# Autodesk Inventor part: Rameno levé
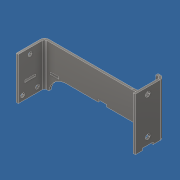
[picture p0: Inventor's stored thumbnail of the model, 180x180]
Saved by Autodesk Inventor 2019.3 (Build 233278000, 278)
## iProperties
Created: 2019-02
Part Number: Rameno levé
Material: Nerezová ocel, austenitická
Document SubType Name: Plech
Designer: B-hon
Density: 8 g/cm^3
Sheet Metal Rule: Výchozí_mm
Appearance: Pololeštěná
Author: B-hon
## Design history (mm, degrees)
node "Plocha3"
  sketch "Náčrt4"
    geometry: L1 (0, 0)-(169, 0); L2 (169, 0)-(169, 95); L3 (169, 95)-(0, 95); L4 (0, 95)-(0, 0)
    constraints: 8 end point, 2 parallel, 1 horizontal, 1 perpendicular
    dimensions: "d21" = 169 distance of L3.end L2.end; "d22" = 95 distance of L2.end L1.end
node "Obruba2"
node "Obruba3"
sketch "Náčrt7"
  geometry: L1 (-8.449, 60)-(-3.667, 60); L2 (-3.667, 60)-(-3.667, 60); L3 (-3.667, 60)-(160, 60); L4 (160, 60)-(160, 100.088); L5 (160, 100.088)-(-8.679, 99.094); L6 (-8.679, 99.094)-(-8.449, 60); L7 (6, 95)-(6, 0) reference; L8 (163, 0)-(163, 95) reference; L9 (163, 0)-(6, 0) reference; 1 further point
  constraints: 12 end point, 4 perpendicular, 1 horizontal
  dimensions: "d45" = 3 distance between parallel lines of L8 L4; "d46" = 60 distance between parallel lines of L9 L3; "d47" = 60 distance between parallel lines of L9 L1
extrude "Vysunutí1" cut sketch "Náčrt7" stored distance "d48" = 100; taper "d49" = 0 deg
fillet "Zaoblení2" dims "d51" = 35
sketch "Náčrt8"
  geometry: L1 (9, 21)-(200.584, 21); L2 (200.584, 21)-(200.584, -6.662); L3 (200.584, -6.662)-(9, -6.662); L4 (9, -6.662)-(9, 21); L5 (125, 60)-(6, 60) reference; L6 (6, 60)-(6, 0) reference; 1 further point
  constraints: 8 end point, 2 parallel, 1 horizontal, 1 perpendicular
  dimensions: "d52" = 39 distance between parallel lines of L5 L1; "d53" = 3 distance between parallel lines of L6 L4
extrude "Vysunutí2" cut sketch "Náčrt8" stored distance "d54" = 100; taper "d55" = 0 deg
fillet "Zaoblení3" dims "d56" = 25
sketch "Náčrt9"
  geometry: L1 (0, 0)-(0, 95) reference; L2 (34, 0)-(0, 0) reference; 5 further points
  constraints: 1 horizontal alignment
  dimensions: "d57" = 6 distance from line of L1 point (6, 7); "d58" = 21 distance of point (27, 7) point (6, 7); "d59" = 7 distance from line of L2 point (6, 7); "d60" = 45 vertical distance of point (27, 7) point (16.5, 52); "d61" = 10.5 horizontal distance of point (27, 7) point (16.5, 52) (= 0.5 x d58)
hole "Díra1" sketch "Náčrt9" at (16.5, 52), (27, 7), (6, 7) diameter "d62" = 5.5; stored, may be unused: countersink angle "d66" = 90 deg, drill point angle "d68" = 118 deg; dims "d63" = 12, "d64" = 4, "d65" = 2, "d67" = 3 (= Tloušťka)
sketch "Náčrt10"
  geometry: L1 (0, 0)-(35, 0) reference; C1 r 2.75 at (28, -88) reference; C2 r 2.75 at (7, -88) reference; C3 r 2.75 at (17.5, -43) reference; 3 further points
  constraints: 2 vertical alignment
  dimensions: "d69" = 9 distance from line of point (17.5, -9) L1; "d70" = 52 distance of point (17.5, -61) point (17.5, -9)
hole "Díra2" sketch "Náčrt10" at (17.5, -61), (17.5, -9) diameter "d71" = 6.6; stored, may be unused: countersink angle "d75" = 90 deg, drill point angle "d77" = 118 deg; dims "d72" = 12, "d73" = 4, "d74" = 2, "d76" = 3 (= Tloušťka)
sketch "Náčrt15"
  geometry: L1 (-163, 21)-(-33.678, 21) reference; L2 (-158, 24)-(-146, 24); L3 (-146, 24)-(-146, 21); L4 (-146, 21)-(-158, 21); L5 (-158, 21)-(-158, 24); L6 (-163, 95)-(-163, 21) reference; 1 further point
  constraints: 8 end point, 2 parallel, 1 horizontal, 1 perpendicular, 1 point on line
  dimensions: "d104" = 12 distance of L3.end L4.end; "d105" = 3 distance of L2.end L3.end; "d106" = 5 distance between parallel lines of L6 L5
extrude "Vysunutí7" cut sketch "Náčrt15" distance "d107" = 300; taper "d108" = 0 deg
pattern_linear "Obdélníkové pole3" dims "d111" = 67.5
sketch "Náčrt16"
  geometry: L1 (10, -71)-(25, -71); L2 (25, -71)-(25, -74); L3 (25, -74)-(10, -74); L4 (10, -74)-(10, -71); L5 (0, -74)-(35, -74) reference; L6 (-3, -74)-(-3, 0) reference; 2 further points
  constraints: 8 end point, 2 parallel, 1 horizontal, 1 perpendicular
  dimensions: "d112" = 0 distance between parallel lines of L5 L3; "d113" = 3 distance of L1.end L2.end; "d114" = 15 distance of L2.end L3.end; "d115" = 13 distance between parallel lines of L6 L4
extrude "Vysunutí8" cut sketch "Náčrt16" stored distance "d116" = 500; taper "d117" = 0 deg
node "Těleso3"
feature "Deska4" dims "d23" = 3 (= Tloušťka)
sketch "Náčrt5"
  geometry: L1 through (47.5, 0) direction (-1, 0); L2 through (0, -20) direction (0, -1); L3 (0, -40)-(95, -40); L4 (95, -40)-(95, 0)
  constraints: 6 end point, 1 horizontal, 1 perpendicular, 1 vertical
feature "Deska5" dims "d23" = 3 (= Tloušťka), "d24" = 3 (= ŠířkaVýštipu), "d25" = 1.5 (= HloubkaVýštipu), "d26" = 6 (= MinimálníZbytek), "d27" = 3 (= PřechodovýPoloměr), "d28" = 40, "d29" = -90 deg, "d30" = 3 (= PoloměrOhybu), "d31" = 12 (= VelikostRohovéhoVýštipu), "d32" = 3 (= VelikostMezery), "d33" = 3 (= VelikostJacobihoPoloměru), "MezeraVystřižení" = 0.01
feature "Ohyb2" dims "d23" = 3 (= Tloušťka), "d24" = 3 (= ŠířkaVýštipu), "d25" = 1.5 (= HloubkaVýštipu), "d26" = 6 (= MinimálníZbytek), "d27" = 3 (= PřechodovýPoloměr), "d28" = 40, "d29" = -90 deg, "d30" = 3 (= PoloměrOhybu), "MezeraVystřižení" = 0.01
feature "Roh2" dims "d28" = 40, "d29" = -90 deg, "d31" = 12 (= VelikostRohovéhoVýštipu), "d32" = 3 (= VelikostMezery), "d33" = 3 (= VelikostJacobihoPoloměru)
sketch "Náčrt6"
  geometry: L1 through (47.5, 0) direction (-1, -0); L2 through (0, -20.5) direction (2.41e-32, -1); L3 (0, -41)-(95, -41); L4 (95, -41)-(95, 0)
  constraints: 6 end point, 1 horizontal, 1 perpendicular, 1 vertical
feature "Deska6" dims "d23" = 3 (= Tloušťka), "d34" = 3 (= ŠířkaVýštipu), "d35" = 1.5 (= HloubkaVýštipu), "d36" = 6 (= MinimálníZbytek), "d37" = 3 (= PřechodovýPoloměr), "d38" = 41, "d39" = -90 deg, "d40" = 3 (= PoloměrOhybu), "d41" = 12 (= VelikostRohovéhoVýštipu), "d42" = 3 (= VelikostMezery), "d43" = 3 (= VelikostJacobihoPoloměru), "MezeraVystřižení" = 0.01
feature "Ohyb3" dims "d23" = 3 (= Tloušťka), "d34" = 3 (= ŠířkaVýštipu), "d35" = 1.5 (= HloubkaVýštipu), "d36" = 6 (= MinimálníZbytek), "d37" = 3 (= PřechodovýPoloměr), "d38" = 41, "d39" = -90 deg, "d40" = 3 (= PoloměrOhybu), "MezeraVystřižení" = 0.01
feature "Roh3" dims "d38" = 41, "d39" = -90 deg, "d41" = 12 (= VelikostRohovéhoVýštipu), "d42" = 3 (= VelikostMezery), "d43" = 3 (= VelikostJacobihoPoloměru)
other parameters: "Tloušťka" = 3 (derived), "KSoučinitel" = 4.4, "PoloměrOhybu" = 3 (= Tloušťka), "ŠířkaVýštipu" = 3 (= Tloušťka), "HloubkaVýštipu" = 1.5 (= 0.5 x Tloušťka), "VelikostRohovéhoVýštipu" = 12 (= 4 x Tloušťka), "MinimálníZbytek" = 6 (= 2 x Tloušťka), "PřechodovýPoloměr" = 3 (= PoloměrOhybu), "VelikostJacobihoPoloměru" = 3 (= PoloměrOhybu), "VelikostMezery" = 3 (= Tloušťka)
